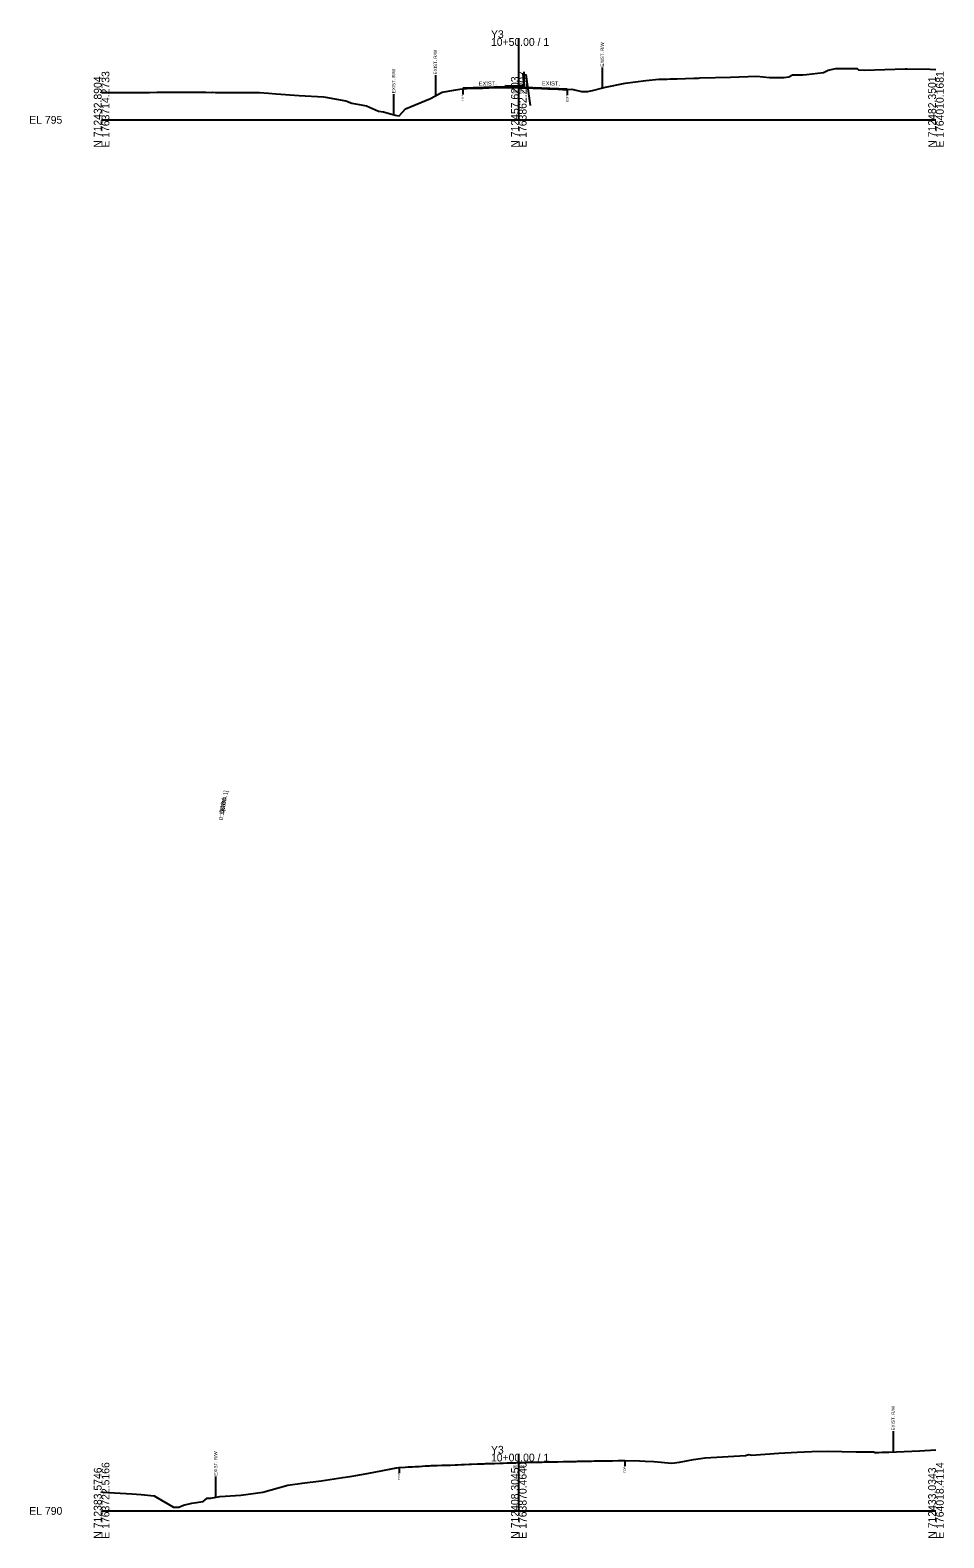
# Model space of a CAD drawing. Extents: x -26 to 2903, y -10 to 5022.
# Drawn here: x -26 to 303, y -10 to 532 of the extents above; entities that cross this region are included whole.
import ezdxf

# ---------------------------------------------------------------- set-up
doc = ezdxf.new("R2010")
doc.units = 0
for name, color, linetype in [('Default', 7, 'Continuous'), ('Exist Cross Section Cell', 7, 'Continuous'), ('Exist XS Center Line Elevation Label', 7, 'Continuous'), ('Exist XS Ground Line', 7, 'Continuous'), ('Old_Level_10', 7, 'Continuous'), ('Prop CMT Pvmt Course 1', 7, 'Continuous'), ('Prop CMT Pvmt Surface', 7, 'Continuous'), ('Prop XS Conc Monolithic Island', 7, 'Continuous'), ('Prop XS SE Text', 7, 'Continuous'), ('Prop XS Side Slope Text', 7, 'Continuous'), ('Scratch_Level_4', 7, 'Continuous')]:
    doc.layers.add(name, color=color, linetype=linetype)

msp = doc.modelspace()

# ---------------------------------------------------------------- linework, layer by layer
at = {"layer": 'Exist Cross Section Cell'}
for p, q in [((150, 500), (150, 529.39)), ((0, 500), (150, 500)), ((150, 500), (300, 500)), ((150, 0), (150, 20.56)), ((0, 0), (150, 0)), ((150, 0), (300, 0))]:
    msp.add_line(p, q, dxfattribs=at)
at = {"layer": 'Exist XS Ground Line'}
for points in [[(0, 509.8), (0.91, 509.8), (2.46, 509.79), (4.53, 509.8), (5.21, 509.8), (7.07, 509.8), (8.98, 509.85), (9.61, 509.85), (10.49, 509.85), (12.14, 509.86), (13.32, 509.86), (14.68, 509.85), (16.58, 509.87), (17.21, 509.88), (19.84, 509.91), (20.38, 509.91), (22, 509.91), (23.31, 509.93), (24.09, 509.93), (27.5, 509.9), (28.52, 509.9), (29.89, 509.9), (30.7, 509.9), (32.42, 509.91), (32.87, 509.91), (35.04, 509.9), (35.54, 509.9), (37.49, 509.9), (39.38, 509.88), (40.02, 509.89), (40.92, 509.88), (42.56, 509.88), (43.73, 509.87), (45.09, 509.86), (47.01, 509.87), (47.63, 509.87), (48.07, 509.87), (50.24, 509.87), (50.72, 509.87), (52.31, 509.85), (55.89, 509.88), (56.78, 509.82), (60.01, 509.62), (62.72, 509.39), (71.03, 508.8), (79.82, 508.23), (80.52, 508.18), (87.84, 506.88), (89.94, 506.05), (95.2, 505.09), (99.6, 503.17), (101.34, 502.88), (105.55, 501.72), (106.3, 501.57), (106.98, 501.47), (109.27, 503.91), (118.21, 507.63), (122.4, 509.99), (127.35, 510.76), (128.83, 511), (129.83, 511.18), (130.41, 511.22), (131.27, 511.27), (132.76, 511.34), (133.81, 511.36), (134.94, 511.38), (136.34, 511.4), (137.11, 511.43), (138.88, 511.5), (139.28, 511.51), (141.45, 511.57), (142.6, 511.59), (143.03, 511.59), (143.57, 511.6), (144.06, 511.62), (144.55, 511.6), (146.48, 511.56), (147.97, 511.57), (149.02, 511.58), (150.14, 511.55), (151.55, 511.52), (152.31, 511.5), (154.2, 511.45), (154.67, 511.46), (155.78, 511.57), (156.85, 511.35), (158.82, 511.27), (160.48, 511.17), (164.12, 510.99), (165.7, 510.91), (166.95, 510.83), (167.43, 510.87), (169.05, 510.98), (172.6, 510.19), (174.8, 510.21), (175.36, 510.29), (176.56, 510.52), (180.23, 511.46), (181.21, 511.69), (188.26, 513.19), (195.69, 514.09), (200.37, 514.67), (201.54, 514.67), (203.39, 514.67), (204.49, 514.68), (206.27, 514.75), (206.94, 514.78), (212.93, 514.99), (213.34, 515.01), (214.63, 515.01), (215.22, 515.1), (226.13, 515.37), (235.57, 515.7), (240.17, 515.22), (245.34, 515.17), (247.07, 515.43), (248.47, 516.16), (252.09, 516.17), (253.46, 516.29), (259.52, 516.98), (261.28, 517.91), (263.94, 518.44), (265.69, 518.44), (267.85, 518.44), (271.69, 518.45), (272.11, 517.95), (274.35, 517.89), (288.96, 518.29), (289.67, 518.3), (297.93, 518.17), (300, 518.15)], [(0, 6.85), (0.43, 6.77), (10.88, 6.18), (14.28, 5.93), (18.86, 5.43), (21.5, 3.89), (23.78, 2.57), (25.85, 1.3), (26.25, 1.31), (27.73, 1.36), (29.44, 2), (32.4, 2.81), (36.49, 3.4), (37.98, 4.61), (39.22, 4.57), (42.56, 5.21), (50.08, 5.7), (57.92, 6.71), (66.91, 9.21), (72.16, 9.93), (78.94, 10.8), (86.72, 12.04), (89.24, 12.36), (91.45, 12.67), (95.48, 13.44), (101.1, 14.52), (105.89, 15.42), (106, 15.46), (106.15, 15.47), (106.95, 15.63), (109.13, 15.75), (110.17, 15.8), (110.88, 15.84), (111.73, 15.88), (112.78, 15.92), (114.15, 16.01), (115.31, 16.07), (116.32, 16.14), (117.85, 16.23), (118.49, 16.27), (120.38, 16.35), (120.67, 16.36), (122.37, 16.39), (122.84, 16.4), (122.92, 16.4), (125.01, 16.47), (125.45, 16.48), (127.18, 16.56), (127.98, 16.58), (129.35, 16.63), (130.52, 16.68), (132.15, 16.74), (133.05, 16.78), (135.2, 16.86), (135.59, 16.87), (137.54, 16.96), (138.04, 16.99), (138.12, 16.99), (140.21, 17.05), (140.66, 17.06), (141.28, 17.09), (143.19, 17.15), (144.33, 17.19), (145.73, 17.25), (146.73, 17.27), (148.26, 17.3), (148.9, 17.32), (150, 17.36), (150.8, 17.39), (152.7, 17.44), (153.24, 17.45), (153.33, 17.45), (155.41, 17.5), (155.87, 17.49), (157.58, 17.53), (158.4, 17.56), (159.76, 17.57), (160.94, 17.59), (161.93, 17.62), (163.47, 17.66), (164.1, 17.67), (166.01, 17.71), (166.27, 17.72), (167.87, 17.75), (168.44, 17.76), (168.54, 17.76), (170.61, 17.8), (171.07, 17.81), (172.79, 17.84), (173.61, 17.85), (174.96, 17.89), (176.14, 17.92), (177.13, 17.94), (178.68, 17.95), (179.3, 17.96), (181.21, 18), (181.47, 18.01), (183.03, 18.02), (183.65, 18.02), (183.7, 18.02), (185.78, 18.06), (186.52, 18.07), (186.87, 18.08), (187.43, 18.08), (187.74, 18.08), (188.09, 18.08), (193.37, 17.94), (195.49, 17.88), (198.59, 17.8), (205.09, 17.16), (207.82, 17.53), (212.79, 18.44), (216.98, 19.01), (231.51, 19.93), (232.75, 20.27), (233.67, 20.05), (243.47, 20.69), (250.12, 21.07), (255.42, 21.3), (261.04, 21.44), (266.21, 21.36), (271.37, 21.19), (277.64, 21.23), (277.9, 21.02), (278, 21.02), (279.34, 21.03), (280.52, 21.06), (280.68, 21.06), (280.83, 21.07), (283.04, 21.15), (294.11, 21.61), (300, 21.9)], [(0, 6.85), (0.43, 6.77), (10.88, 6.18), (14.28, 5.93), (18.86, 5.43), (21.5, 3.89), (23.78, 2.57), (25.85, 1.3), (26.25, 1.31), (27.73, 1.36), (29.44, 2), (32.4, 2.81), (36.49, 3.4), (37.98, 4.61), (39.22, 4.57), (42.56, 5.21), (50.08, 5.7), (57.92, 6.71), (66.91, 9.21), (72.16, 9.93), (78.94, 10.8), (86.72, 12.04), (89.24, 12.36), (91.45, 12.67), (95.48, 13.44), (101.1, 14.52), (106.15, 15.47), (106.95, 15.63), (109.13, 15.75), (110.17, 15.8), (110.88, 15.84), (111.73, 15.88), (112.78, 15.92), (114.15, 16.01), (115.31, 16.07), (116.32, 16.14), (117.85, 16.23), (118.49, 16.27), (120.67, 16.36), (122.37, 16.39), (122.92, 16.4), (125.01, 16.47), (125.45, 16.48), (127.18, 16.56), (127.98, 16.58), (129.35, 16.63), (130.52, 16.68), (132.15, 16.74), (133.05, 16.78), (135.2, 16.86), (135.59, 16.87), (137.54, 16.96), (138.12, 16.99), (140.21, 17.05), (140.66, 17.06), (141.28, 17.09), (143.19, 17.15), (144.33, 17.19), (145.73, 17.25), (146.73, 17.27), (148.26, 17.3), (148.9, 17.32), (150, 17.36), (150.8, 17.39), (152.7, 17.44), (153.33, 17.45), (155.41, 17.5), (155.87, 17.49), (157.58, 17.53), (158.4, 17.56), (159.76, 17.57), (160.94, 17.59), (161.93, 17.62), (163.47, 17.66), (164.1, 17.67), (166.27, 17.72), (167.87, 17.75), (168.54, 17.76), (170.61, 17.8), (171.07, 17.81), (172.79, 17.84), (173.61, 17.85), (174.96, 17.89), (176.14, 17.92), (177.13, 17.94), (178.68, 17.95), (179.3, 17.96), (181.47, 18.01), (183.03, 18.02), (183.7, 18.02), (185.78, 18.06), (186.52, 18.07), (186.87, 18.08), (187.43, 18.08), (187.74, 18.08), (188.09, 18.08), (193.37, 17.94), (195.49, 17.88), (198.59, 17.8), (205.09, 17.16), (207.82, 17.53), (212.79, 18.44), (216.98, 19.01), (231.51, 19.93), (232.75, 20.27), (233.67, 20.05), (243.47, 20.69), (250.12, 21.07), (255.42, 21.3), (261.04, 21.44), (266.21, 21.36), (271.37, 21.19), (277.64, 21.23), (277.9, 21.02), (279.34, 21.03), (280.83, 21.07), (283.04, 21.15), (294.11, 21.61), (300, 21.9)]]:
    msp.add_lwpolyline(points, dxfattribs=at)
at = {"layer": 'Old_Level_10'}
for p, q in [((120, 516.04), (120, 508.64)), ((180, 518.8), (180, 511.4)), ((129.83, 511.18), (129.83, 509.12)), ((167.43, 510.87), (167.43, 508.82)), ((105.01, 509.27), (105.01, 501.87)), ((284.61, 28.62), (284.61, 21.22)), ((188.09, 18.08), (188.09, 16.03)), ((41.01, 12.31), (41.01, 4.91)), ((106.95, 15.63), (106.95, 13.58))]:
    msp.add_line(p, q, dxfattribs=at)
at = {"layer": 'Prop CMT Pvmt Course 1'}
for points in [[(144.89, 511.85), (129.83, 511.43)], [(144.89, 511.6), (129.83, 511.18)], [(150.14, 511.55), (150.14, 511.55), (150.14, 511.55)], [(151.94, 511.76), (167.43, 511.12)], [(151.94, 511.51), (167.43, 510.87)]]:
    msp.add_lwpolyline(points, dxfattribs=at)
at = {"layer": 'Prop CMT Pvmt Surface'}
for points in [[(144.89, 511.85), (129.83, 511.43)], [(151.94, 511.76), (167.43, 511.12)]]:
    msp.add_lwpolyline(points, dxfattribs=at)
at = {"layer": 'Prop XS Conc Monolithic Island'}
for p, q in [((144.89, 511.85), (145.24, 512.21)), ((144.89, 511.6), (144.89, 511.85)), ((151.94, 511.51), (144.89, 511.6)), ((145.36, 512.26), (151.47, 512.17)), ((151.94, 511.76), (151.59, 512.12)), ((151.94, 511.51), (151.94, 511.76))]:
    msp.add_line(p, q, dxfattribs=at)
for centre, start, end in [((145.36, 512.1), 90, 135.9991), ((151.47, 512.01), 44.0009, 90)]:
    msp.add_arc(centre, 0.167, start, end, dxfattribs=at)
at = {"layer": 'Scratch_Level_4'}
for p, q in [((151.94, 511.55), (151.57, 516.79)), ((151.94, 511.55), (151.94, 517.3)), ((151.94, 511.55), (151.94, 516.79)), ((152.57, 516.3), (154.08, 505.1))]:
    msp.add_line(p, q, dxfattribs=at)
for points in [[(150.14, 511.68), (129.83, 511.3)], [(150.14, 511.68), (167.44, 511)]]:
    msp.add_lwpolyline(points, dxfattribs=at)

# ---------------------------------------------------------------- texts
at = {"layer": 'Default'}
for p in [(0, 500), (0, 0)]:
    msp.add_text('-', height=0.0001, dxfattribs=at).set_placement(p)
at = {"layer": 'Exist Cross Section Cell'}
for s, p in [('Y3', (140, 529.39)), ('10+50.00 / 1', (140, 526.59)), ('EL 795', (-26, 498.6)), ('Y3', (140, 20.56)), ('10+00.00 / 1', (140, 17.76)), ('EL 790', (-26, -1.4))]:
    msp.add_text(s, height=2.8, dxfattribs=at).set_placement(p)
for s, p in [('N 712432.8904', (0, 490)), ('E 1763714.2733', (2.8, 490)), ('N 712457.6203', (150, 490)), ('E 1763862.2207', (152.8, 490)), ('N 712482.3501', (300, 490)), ('E 1764010.1681', (302.8, 490)), ('E 1763722.5166', (2.8, -10)), ('E 1763870.4640', (152.8, -10)), ('E 1764018.4114', (302.8, -10)), ('N 712383.5746', (0, -10)), ('N 712408.3045', (150, -10)), ('N 712433.0343', (300, -10))]:
    msp.add_text(s, height=2.8, rotation=90, dxfattribs=at).set_placement(p)
at = {"layer": 'Exist XS Center Line Elevation Label'}
for s, p in [('806.56', (147.86, 509.56)), ('807.36', (147.86, 15.36))]:
    msp.add_text(s, height=1, dxfattribs=at).set_placement(p)
at = {"layer": 'Old_Level_10'}
for s, height, p in [('EXIST. R/W', 1.181, (180.59, 519.11)), ('EXIST. R/W', 1.181, (120.59, 516.34)), ('EXIST. R/W', 1.181, (105.6, 509.57)), ('EOP', 0.787, (130.22, 506.73)), ('EOP', 0.787, (167.82, 506.42)), ('EXIST. R/W', 1.181, (285.2, 28.92)), ('EXIST. R/W', 1.181, (41.6, 12.61)), ('EOP', 0.787, (107.34, 11.18)), ('EOP', 0.787, (188.49, 13.64))]:
    msp.add_text(s, height=height, rotation=90, dxfattribs=at).set_placement(p)
at = {"layer": 'Prop XS SE Text'}
for rotation, p in [(1.0599, (135.58, 512.24)), (359.513, (158.27, 512.38))]:
    msp.add_text('EXIST.', height=1.5, rotation=rotation, dxfattribs=at).set_placement(p)
at = {"layer": 'Prop XS Side Slope Text'}
for s, p in [('0:1 [RUN:1]', (43.56, 248.15)), ('0.18:1', (43.76, 250.72)), ('563%', (44, 250.63))]:
    msp.add_text(s, height=1.5, rotation=79.9302, dxfattribs=at).set_placement(p)

doc.saveas('drawing.dxf')
